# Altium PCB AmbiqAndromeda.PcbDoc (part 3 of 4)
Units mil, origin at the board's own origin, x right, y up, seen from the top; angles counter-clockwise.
Board outline 4055.04 x 2407.2 mil, 6 copper layers (Layer 1, Layer 2, Layer 3, Layer 4, Layer 5, Layer 6), stack 76.457 mil thick; 255 components, 215 nets, 1186 pads, 683 vias.
Unrouted connection lines stored in the file: 258.
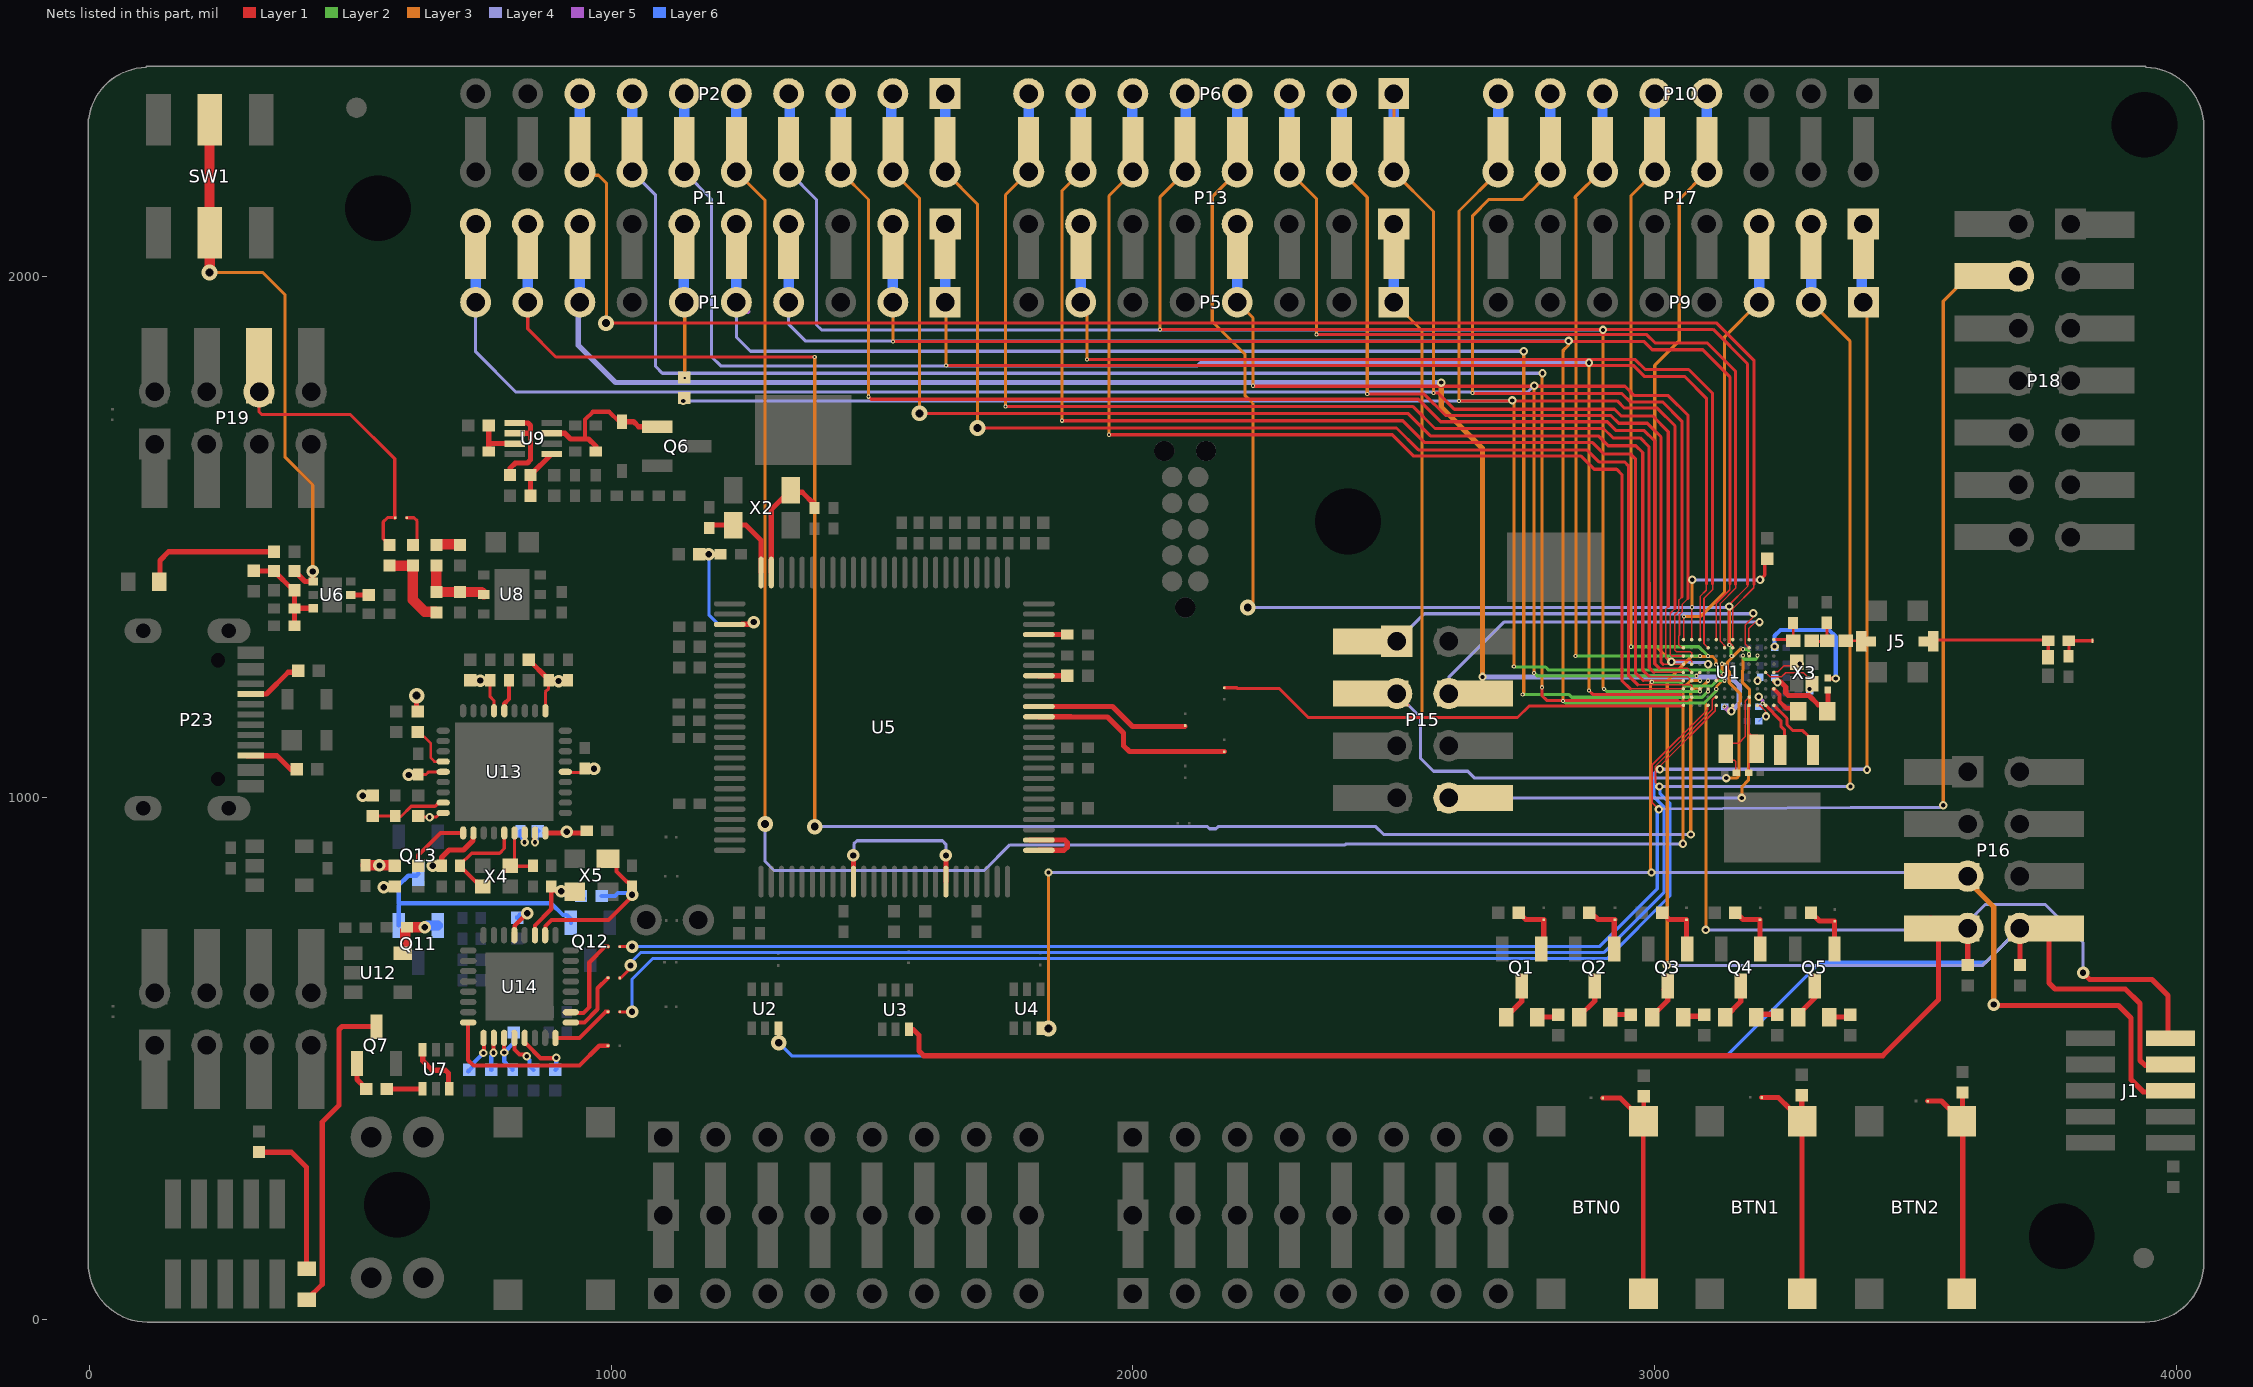
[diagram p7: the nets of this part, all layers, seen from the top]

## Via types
v1: diameter 30, hole 15, Layer 1 to Layer 6, tented both sides, 227 vias
v2: diameter 8, hole 4, Layer 1 to Layer 2, tented both sides, 113 vias
v3: diameter 8, hole 4, Layer 2 to Layer 3, tented both sides, 98 vias
v4: diameter 24, hole 12, Layer 1 to Layer 6, tented both sides, 91 vias
v5: diameter 16, hole 8, Layer 3 to Layer 4, tented both sides, 71 vias
v6: diameter 8, hole 4, Layer 5 to Layer 6, tented both sides, 26 vias
v7: diameter 16, hole 8, Layer 1 to Layer 6, tented both sides, 25 vias
v8: diameter 8, hole 4, Layer 4 to Layer 5, tented both sides, 20 vias
v9: diameter 8, hole 4, Layer 1 to Layer 2, 4 vias
v10: diameter 8, hole 4, Layer 2 to Layer 3, 4 vias
v11: diameter 16/16/16/16/16/16 (per signal layer), hole 8, Layer 1 to Layer 6, tented both sides, 2 vias
v12: diameter 24/0/0/24/24/24 (per signal layer), hole 12, Layer 1 to Layer 6, tented both sides, 1 vias
v13: diameter 30/0/0/30/30/30 (per signal layer), hole 15, Layer 1 to Layer 6, tented both sides, 1 vias

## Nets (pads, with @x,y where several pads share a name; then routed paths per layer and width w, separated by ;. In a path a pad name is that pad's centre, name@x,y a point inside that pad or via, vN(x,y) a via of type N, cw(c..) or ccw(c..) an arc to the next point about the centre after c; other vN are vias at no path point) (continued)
HUB_3.3V: C48.2 C51.2 C59.2 C60.2 C61.2 C62.2 C63.2 C64.2 C65.2 Q11.2 R26.2 R45.2 R46.2 R47.2 R50.2 R59.2 U12.5 U13.5 U13.10 U13.15 U13.23 U13.27 U13.29 U13.36 | length 749.3
  Layer 1 w3: v4@604.36,1047.64 608,1044 v4(612,1044)
  Layer 1 w6: U12.5@600.24,702.4 604.4,702.4 U12.5@605,703 ; v4@606,1046 v4@608,1044 ; v4(612,1044) 629,1044 C61.2@630,1045 645,1045 650,1050 U13.23@677.87,1050 ; R47.2@630,965.31 630,963.35 664.56,963.35 672.48,971.26 U13.27@677.87,971.26 ; C62.2@768,1223.35 768,1193.63 775.31,1186.32 U13.15@775.31,1167.13 ; U13.10@873.74,1167.13 873.74,1203.31 880,1209.57 C65.2@880,1225.31 ; U13.5@912.13,1050 908,1050 907,1049 942.16,1049 949,1055.84 C64.2@949,1056.31
  Layer 1 w10: v1(627,1196) 627,1170.51 ccw(c633.83,1170.51) R50.2@629,1165.69 ; C60.2@675,869.69 675,886 689,900 717.01,900 735.17,918.15 735.17,924.71 735.94,925.49 U13.29@735.94,932.87 ; R45.2@842,1264.69 879.03,1227.65 cw(c876.69,1225.31) C65.2@880,1225.31 ; U13.36@874.61,932 U13.36@873.74,932.87 943.35,932.87 ccw(c943.35,946.96) C59.2@953.31,937
  Layer 1 w20: C48.2@529,870.69 582.59,870.69 cw(c582.59,867.27) R59.2@585,869.69 ; U12.5@605,703 605,745.2 606.87,747.07 606.87,751.84 607.03,752 v4(642.76,752)
  Layer 6 w20: v4(642.76,752) cw(c651.05,743.71) 651.05,755.43 Q11.2@667.4,755.43
  other v4: 658,870 555.79,870.69 915,935 524,1004 967,1056 899,1224 749,1225
  other v7: 652,963
I2SB_NCE46_CT24_SCCRST_PDMC_TX1_SWO_GP46: P5.7 P13.13 U1.H9 | length 2000.4
  Layer 1 w3: U1.H9@3102.33,1287.7 3094.47,1295.55 3094.47,1382.47 3111,1399 3111,1410
  Layer 1 w6: v2(1912,1840) 2963,1840 2982,1821 3065,1821 3111,1775 3111,1410
  Layer 2 w3: P5.7@1891.49,1941.49 P5.7@1900,1950
  Layer 3 w6: P5.7@1900,1950 1912,1938 v2(1912,1840)
  Layer 6 w20: P5.7@1900,1950 1900.16,1950.16 P13.13@1900.16,2100
  other v3: 1912,1840
I2SW_NCE28_CT7_M2MOSI_TX0_GP28: P18.4 SB27.2 U1.A9 | length 4123.8
  Layer 1 w3: v2(3008,978) 2995.5,990.5 2995.5,1063.46 3101.66,1169.62 3101.66,1176.79 U1.A9@3102.33,1177.46
  Layer 1 w6: SB27.2@1016.19,714.88 v4@1039.88,714.88
  Layer 3 w6: v7(3553,986) 3553,990 3553.09,990.09 3553.09,999.43 3553,999.51 3553,1952 3601,2000 P18.4@3697.02,2000
  Layer 4 w6: v8@3009,979 3374.99,981.57 3546.57,981.57 v7@3555,990
  Layer 6 w6: v4(1040,715) 1888.27,715 2894,715 3005,826 3005,974 v6@3009,978 ; P18.4@3694.02,2003 P18.4@3697.02,2000 P18.4@3695.02,1998
  other v3: 3008,978
  other v5: 3008,978
  other v6: 3008,978
  other v8: 3008,978
LV_EN: P19.6 R23.1 SB1.2 | length 575
  Layer 1 w6: P19.6@325,1828.25 P19.6@325,1778.25 325,1740 330,1735 500,1735 585,1650 SB1.2@585,1537.12 ; R23.1@575,1484.69 563,1496.69 563,1529 571.12,1537.12 SB1.2@585,1537.12 ; SB1.2@585,1536 SB1.2@585,1537.12 ; SB1.2@585.81,1537.12 SB1.2@585,1537.12
M0SCL_M0SCK_RTS0_EXHFA_CT8_GP5: P1.6 P11.11 R4.1 | length 297.9
  Layer 1 w20: R4.1@1140,1805.94 1140.93,1805.94 1141,1806 v2(1141,1805)
  Layer 3 w6: v2(1141,1805) P1.6@1141,1949
  Layer 3 w20: P1.6@1140,1950 P1.6@1141,1949
  Layer 6 w10: P1.6@1138.91,1951.09 P1.6@1140,1950
  Layer 6 w20: P1.6@1138.91,1951.09 P11.11@1138.91,2100
  other v3: 1141,1805
M0SDA_M0MISO_CTS0_CT10_I2SD_GP6: P1.5 P11.9 U1.C9 | length 2766.9
  Layer 1 w3: v2(3102,1204) 3102.16,1204.16 3102.16,1208.84 U1.C9@3102.04,1208.96
  Layer 5 w10: P1.5@1257.84,1932.16 P1.5@1262,1932.16
  Layer 2 w6: v3(2747,1198) 2836,1198 2839.81,1194.19 2839.92,1194.19 2841.1,1193 3091,1193 v2(3102,1204)
  Layer 3 w6: v3(2747,1198) 2749,1200 v5(2749,1856)
  Layer 4 w6: P1.5@1240,1950 1240,1883 1267,1856 v5(2749,1856)
  Layer 6 w20: P1.5@1240,1950 P11.9@1240,2100
M1SCL_M1SCK_NCE8_SCCCLK_TX1_GP8: P1.10 P11.19 U1.E10 | length 3190.6
  Layer 1 w3: v2@3078,1234.16 v2@3078.16,1234 ; v2(3080,1234) v2@3078.16,1234 ; U1.E10@3087,1240 3086.58,1240.42 3079.16,1233 v2@3078.16,1234
  Layer 2 w6: v3@2767.91,1239 v3(2768.63,1239.73) 2769.18,1239.73 2774.9,1234 v2(3080,1234)
  Layer 3 w6: v3(2768.63,1239.73) 2768.63,1789.63 v5(2769,1790)
  Layer 4 w6: P1.10@740,1950 740,1855 817,1778 2757,1778 v5(2769,1790)
  Layer 6 w20: P1.10@740,1950 P11.19@740,2100
M1SDA_M1MISO_NCE9_SCCIO_RX1_GP9: P1.9 P11.17 U1.D9 | length 3682.4
  Layer 1 w6: P1.9@840,1950 840,1899 894,1845 v2(1390,1845) ; U1.D9@3101.59,1224 v2(3102.33,1224.71)
  Layer 3 w6: v2(1390,1845) v1(1390,945) v1@1392,943 ; v5(3069,930) 3069,1203 3077,1211 3088.62,1211 v2(3102.33,1224.71)
  Layer 4 w6: v1@1392,938 1399,945 2142.79,945 2146.79,941 2159.21,941 2163.21,945 2465.58,945 2480.58,930 3068,930 v5@3069,929
  Layer 6 w20: P1.9@840,1950 P11.17@840,2100
  other v3: 3102.33,1224.71 1390,1845
MCU_ADCREF: C6.2 P1.8 P11.15 U1.A6 | length 3098.8
  Layer 1 w3: v8(3147,1166) 3147.48,1166.48 3147.48,1171.54 3149.57,1173.63 U1.A6@3149.57,1177.46
  Layer 5 w10: v6(3133.98,1175) 3142.98,1166 v8(3147,1166)
  Layer 3 w10: v5(2591,1796) 2591,1749 2670,1670 v5(2670,1232)
  Layer 4 w10: P1.8@940,1950 937,1947 937,1867 1008,1796 v5(2591,1796) ; v5(2670,1232) 3145,1232 3161.97,1215.03 3161.97,1181.02 v8(3147,1166) v5@3146.37,1166.63
  Layer 6 w20: P1.8@940,1950 P11.15@940,2100
  other v2: 3147,1166
  other v3: 3147,1166
  other v5: 3147,1166
MSPI1_0_NCE51_CT1_GP51: P2.7 P11.14 U1.B11 | length 3163
  Layer 1 w3: 3044.62,1187 3046.31,1185.31 3063.31,1185.31 3070.12,1192.12 3070.12,1192.5 U1.B11@3070.83,1193.21
  Layer 1 w6: v2(2784,1212) 2784,1198 2783,1197 2793,1187 3044.62,1187
  Layer 3 w6: v2(2784,1212) 2784,1813 v5(2785,1814)
  Layer 4 w6: P11.14@1040,2200 1085,2155 1085,1827 1098,1814 v5(2785,1814)
  Layer 6 w3: P2.7@1040,2350 P2.7@1040,2352
  Layer 6 w20: P11.14@1040,2200 P2.7@1040,2350
  other v3: 2784,1212
MSPI1_1_NCE52_CT2_GP52: P2.6 P11.12 U1.B12 | length 3035.5
  Layer 1 w3: 3050.29,1198 U1.B12@3055.08,1193.21
  Layer 1 w6: v2(2874,1206) 2882,1198 3050.29,1198
  Layer 3 w6: v2(2874,1206) 2874,1805 ; 2874,1807 v5(2874,1834)
  Layer 4 w6: P11.12@1140,2200 1192,2148 1192,1846 1210,1828 2123.25,1828 2129.25,1834 v5(2874,1834)
  Layer 6 w20: P2.6@1140,2350 P11.12@1140,2200 P11.12@1144,2204
  other v3: 2874,1206
MSPI1_2_NCE53_CT3_GP53: P2.5 P11.10 U1.D10 | length 3618.7
  Layer 1 w3: U1.D10@3086.58,1223.42 3086,1224 3086.58,1224.58 v2(3086.58,1224.71)
  Layer 3 w6: P11.10@1240,2200 1295,2145 1295,1734.17 ; v1(1295,950) 1295,1732.5 ; v5(3054,912) 3054,1210 3068.71,1224.71 v2(3086.58,1224.71)
  Layer 4 w6: v1(1295,950) 1295,878 1312,861 1715,861 1764,910 2406.65,910 2408.65,912 v5(3054,912)
  Layer 6 w20: P11.10@1240,2200 P2.5@1240,2350
  other v3: 3086.58,1224.71
MSPI1_3_NCE54_CT4_GP54: P2.4 P11.8 U1.C10 | length 2853.7
  Layer 2 w6: v3(2903,1209) 2908,1204 v2(3087,1204)
  Layer 3 w6: v5(2901,1897) 2901,1211 v3(2903,1209)
  Layer 4 w6: P11.8@1340,2200 1393.49,2146.51 1393.49,1906.51 1403,1897 v5(2901,1897)
  Layer 6 w20: P11.8@1340,2200 1342,2202 1342,2333 1340,2335 P2.4@1340,2350
MSPI1_4_NCE55_CT5_GP55: P2.3 P11.6 U1.E11 | length 2649.8
  Layer 1 w3: 3008.64,1248.36 3062.93,1248.36 U1.E11@3070.83,1240.45
  Layer 1 w6: v2(1493,1769) 1498,1764 2547,1764 2590,1721 2909,1721 2926,1704 2980,1704 2999.99,1684.01 2999.99,1257.01 3008.64,1248.36
  Layer 3 w6: P11.6@1440,2200 1493,2147 v2(1493,1769)
  Layer 6 w20: P11.6@1440,2200 P2.3@1440,2350
  other v3: 1493,1769
MSPI1_5_NCE56_CT6_GP56: P2.2 P11.4 U1.D11 | length 2572.9
  Layer 1 w3: 2989.39,1232.61 3062.93,1232.61 U1.D11@3070.83,1224.71
  Layer 1 w6: v1(1591,1737) 2527,1737 2570,1694 2892,1694 2911,1675 2964,1675 2977,1662 2977,1245 2989.39,1232.61
  Layer 3 w6: P11.4@1540,2200 1591,2149 v1(1591,1737)
  Layer 6 w3: P2.2@1537,2346 1540,2349 P2.2@1540,2350
  Layer 6 w20: P2.2@1537,2346 1537,2203 P11.4@1540,2200
MSPI1_6_NCE57_CT7_GP57: P2.1 P11.2 U1.C11 | length 2481.7
  Layer 1 w3: 2967.2,1216.8 3069.07,1216.8 3070.83,1215.05 U1.C11@3070.83,1208.96
  Layer 1 w6: v1(1702,1709) 2505,1709 2547,1667 2870,1667 2893,1644 2942,1644 2950,1636 2950,1234 2967.2,1216.8
  Layer 3 w6: P11.2@1640,2200 1702,2138 v1(1702,1709)
  Layer 6 w20: P11.2@1640,2200 P2.1@1640,2350
MSPI1_7_NCE58_CT8_GP58: P6.8 P13.16 U1.E12 | length 2376.1
  Layer 1 w3: 2998.5,1240.5 3055.04,1240.5 U1.E12@3055.08,1240.45
  Layer 1 w6: v2(1755.75,1750.25) 1756,1750 2537,1750 2579,1708 2902,1708 2920,1690 2972,1690 2989,1673 2989,1413 ; 2989.49,1413 2989.49,1249.51 2998.5,1240.5
  Layer 3 w6: v2(1755.75,1750.25) 1755.75,2155.75 P13.16@1800,2200
  Layer 6 w20: P13.16@1800,2200 P6.8@1800,2349.99
  other v3: 1755.75,1750.25
MSPI1_8_NCE59_CT9_GP59: P6.7 P13.14 U1.D12 | length 2286.6
  Layer 1 w3: 2978,1225 3054.79,1225 U1.D12@3055.08,1224.71
  Layer 1 w6: v2(1864,1723) 2517,1723 2559,1681 2881,1681 2903,1659 2954,1659 2963,1650 2963,1240 2978,1225
  Layer 3 w6: v2(1864,1723) 1864,2164 P13.14@1900,2200
  Layer 6 w6: P13.14@1900,2193 P13.14@1900,2200
  Layer 6 w20: P13.14@1900,2200 P6.7@1900,2349.99
  other v3: 1864,1723
MSPI1_9_NCE60_CT10_GP60: P6.6 P13.12 U1.C12 | length 2210.1
  Layer 1 w3: 2953.04,1208.96 U1.C12@3055.08,1208.96
  Layer 1 w6: v2(1954,1696) 2497,1696 2538,1655 2859,1655 2884,1630 2927,1630 2937,1620 2937,1225 2953.04,1208.96
  Layer 3 w6: v2(1954,1696) 1954,2154 P13.12@2000,2200
  Layer 6 w6: P6.6@1999,2351 P6.6@2000,2349.99
  Layer 6 w20: P6.6@1999,2351 1999,2201 P13.12@2000,2200
  other v3: 1954,1696
MSPI2_0_NCE64_CT14_GP64: P6.2 P13.4 U1.F12 | length 1700.6
  Layer 1 w3: 3016,1256 3054.88,1256 U1.F12@3055.08,1256.2
  Layer 1 w6: v2(2449,1774) 2558.2,1774 2599.2,1733 2916,1733 2931,1718 2986,1718 3012,1692 3012,1260 3016,1256
  Layer 3 w6: P13.4@2400,2200 2449,2151 v2(2449,1774)
  Layer 6 w3: 2395,2319 2395,2344.99 P6.2@2400,2349.99
  Layer 6 w20: P13.4@2400,2200 P6.2@2400,2347.49
  other v3: 2449,1774
MSPI2_1_NCE65_CT15_GP65: P6.1 P13.2 U1.F11 | length 1733.8
  Layer 1 w3: 3026,1367 3021,1362 3021,1268 3024.95,1264.05 3069.07,1264.05 3070.83,1262.29 U1.F11@3070.83,1256.2
  Layer 1 w6: v2(2576,1776) 2585,1776 2616,1745 2923,1745 2936,1732 2996,1732 3026,1702 3026,1367
  Layer 3 w6: P6.1@2500,2349.99 P13.2@2500,2200 2576,2124 v2(2576,1776)
  Layer 6 w6: P6.1@2500,2349.99 2500,2333 P6.1@2504,2329
  Layer 6 w20: P13.2@2500,2200 2500,2325 P6.1@2504,2329
  other v3: 2576,1776
MSPI2_2_NCE66_CT16_GP66: P10.8 P17.16 U1.G12 | length 1522
  Layer 1 w3: 3039,1363 3030,1354 3030,1275 3033,1272 3055.03,1272 U1.G12@3055.08,1271.95
  Layer 1 w6: v2(2625,1761) 2629,1761 2928,1761 2942,1747 3005,1747 3039,1713 3039,1363
  Layer 3 w6: v2(2625,1761) 2625,2125 P17.16@2700,2200
  Layer 6 w20: P17.16@2700,2200 P10.8@2700,2349.99
  other v3: 2625,1761
MSPI2_3_NCE67_CT17_GP67: P10.7 P17.14 U1.G11 | length 1585.2
  Layer 1 w3: 3042,1279.8 3069.07,1279.8 3070.83,1278.04 U1.G11@3070.83,1271.95 ; 3042,1280 3038.5,1283.5 3038.5,1351.01 3046.5,1359.01 3046.5,1379.5 3052,1385
  Layer 1 w6: v2@2650,1776 2651,1775 2937,1775 2953,1759 3015,1759 3052,1722 3052,1385
  Layer 3 w6: v3@2651,1777 2651,2116 2682,2147 2747,2147 P17.14@2800,2200
  Layer 6 w20: P17.14@2800,2200 2800,2337 2804,2341 2800,2345 P10.7@2800,2349.99
  other v2: 2651,1776
  other v3: 2651,1776
MSPI2_4_NCE68_CT18_GP68: P10.6 P17.12 U1.G10 | length 1348.6
  Layer 1 w3: v2(3086.58,1271.95) 3086.58,1271.42 U1.G10@3087,1271
  Layer 2 w6: v3(2848,1272) 2847.1,1272 2848,1272.9 2848.95,1271.95 v2(3086.58,1271.95)
  Layer 3 w6: v3(2848,1272) 2849,1273 2849,2149 2847,2151 2896,2200 P17.12@2900,2200
  Layer 6 w6: P10.6@2900,2349.99 P10.6@2901.99,2349.99
  Layer 6 w20: P17.12@2900,2200 2900,2348 P10.6@2901.99,2349.99
NCE7_M0MOSI_CKO_TRG0_TX0_CT19_GP7: P1.4 P11.7 U1.C8 | length 2711
  Layer 1 w3: P11.7@1340,2100 P11.7@1346.2,2100
  Layer 2 w6: v3(2824,1186) 2828,1182 3095,1182 3118,1205 v2(3118,1209)
  Layer 3 w6: v3(2824,1186) 2824,1855 2825,1856 2824,1857 2835,1868 v5(2835,1876)
  Layer 4 w6: P1.4@1340,1950 1340,1908 1372,1876 v5(2835,1876)
  Layer 6 w20: P1.4@1340,1950 P11.7@1340,2100
NCE41_BLEIRQ_SWO_I2SW_RTS1_TX0_RTS0_GP41: J1.6 P16.5 U1.D7 U4.3 | length 3378.9
  Layer 1 w6: v1@1838,556 v1(1838,558)
  Layer 1 w10: P16.5@3550,850 P16.5@3600,850 ; v4(3650,604) 3652,602 3889,602 3913,578 3913,460 3936.58,436.42 3986.19,436.42 J1.6@3988.77,439
  Layer 2 w6: v3(2994.5,1222.5) 3048.05,1222.5 3056.05,1214.5 3109.06,1214.5 3119.26,1224.71 v2(3133.82,1224.71)
  Layer 3 w6: v1(1838,558) v5(1838,857) ; v5(2994,857) 2992,859 2992,1219.46 2994.5,1221.96 v3(2994.5,1222.5)
  Layer 3 w10: P16.5@3605.31,835.63 3650,790.94 v4(3650,604)
  Layer 4 w6: v5(1838,857) v5(2994,857) 3593,857 P16.5@3600,850
  Layer 6 w10: P16.5@3600,850 3604.92,850 3605.31,850.39 P16.5@3605.31,835.63
NetA1_1: A1.1 C41.2 C42.1 | length 78.7
  Layer 1 w6.25: C41.2@3790.78,1301.32 C41.2@3794,1301.32 ; C42.1@3793,1271.69 3793,1272.65 3794,1273.65 C41.2@3794,1301.32 ; C41.2@3793.69,1301 C41.2@3794,1301.32 ; A1.1@3839.02,1301.32 C41.2@3794,1301.32
NetBTN0_2: BTN0.2 BTN0.3 R36.1 SB24.2 | length 479.6
  Layer 1 w8: BTN0.3@2953.06,405.88 2955.02,405.88 BTN0.3@2978,382.91 ; BTN0.2@2978.58,49.65 2978,50.23 BTN0.3@2978,382.91 ; R36.1@2979,428.32 2979,380.77 BTN0.3@2978.58,380.35 2978.58,382.32 BTN0.3@2978,382.91
  Layer 1 w10: SB24.2@2900.19,424.88 2934.06,424.88 BTN0.3@2953.06,405.88
NetBTN1_2: BTN1.2 BTN1.3 R37.1 SB25.2 | length 472.4
  Layer 1 w10: SB25.2@3205.19,425.88 3207.18,425.88 3207.3,426 3236.94,426 3258.06,404.88 3260.02,404.88 BTN1.3@3282,382.91 ; R37.1@3282,427.07 BTN1.3@3282,382.91 ; BTN1.2@3282.58,49.65 BTN1.3@3282.58,380.35 3282.58,382.32 BTN1.3@3282,382.91
NetBTN2_2: BTN2.2 BTN2.3 R38.1 SB26.2 | length 799.6
  Layer 1 w10: SB26.2@3523.19,418.88 3523.98,418.88 3524.1,419 3549.94,419 3564.06,404.88 3566.02,404.88 3588.58,382.32 BTN2.3@3588.58,380.35 ; BTN2.2@3588.58,49.65 3590,51.06 R38.1@3590,435.32 ; BTN2.2@3590.58,45.65 BTN2.3@3590.58,376.35
NetC7_2: C7.2 U1.A3 | length 48.9
  Layer 1 w3: U1.A3@3196.81,1177.46 3197.52,1176.75 3202.17,1176.75 3213.25,1165.68 v2(3213.25,1156.25)
  Layer 6 w3: C7.2@3199.33,1147.04 3200.12,1147.04 3204.92,1151.84 3204.92,1152.63 3207.88,1155.6 3212.6,1155.6 v2(3213.25,1156.25)
  other v3: 3213.25,1156.25
  other v5: 3213.25,1156.25
  other v6: 3213.25,1156.25
  other v8: 3213.25,1156.25
NetC8_2: C8.2 U1.B3 | length 19
  Layer 1 w3: U1.B3@3196.81,1193.21 3197.63,1194 v2(3199.31,1194)
  Layer 5 w6: v2(3199.31,1194) 3207,1186.31 v6(3207,1181)
  other v3: 3199.31,1194
  other v5: 3199.31,1194
  other v8: 3199.31,1194
NetC9_2: C9.2 U1.D3 | length 3.4
  Layer 4 w6: v8(3197.05,1224.71) 3198.47,1224.71 3197.76,1224 v8(3197.05,1224.71)
  other v2: 3197.05,1224.71
  other v3: 3197.05,1224.71
  other v5: 3197.05,1224.71
  other v6: 3197.05,1224.71
NetC26_2: C26.2 U5.47 | length 54.7
  Layer 1 w10: U5.47@1819.63,1312.96 C26.2@1874.31,1313 ; C26.2@1874.31,1313 C26.2@1874.31,1313
NetC27_1: C27.1 U5.74 X2.3 | length 237
  Layer 1 w10: U5.74@1306.83,1432.05 1306.83,1552.64 X2.3@1343.84,1589.64 1347.49,1586 1366.26,1586 1389.72,1562.54 C27.1@1389.72,1555.55
NetC28_1: C28.1 U5.75 X2.1 | length 175.5
  Layer 1 w10: C28.1@1187.72,1517.49 1188.49,1517.49 1194,1523 1257.92,1523 1287.15,1493.77 U5.75@1287.15,1432.05
NetC29_2: C29.2 R14.1 U5.78 | length 279
  Layer 1 w10: R14.1@1164.8,1467 v4(1187.06,1467) ; U5.78@1227.11,1332.64 U5.78@1247.33,1332.64 ; U5.78@1250.68,1333 1269,1333 v12(1273,1337)
  Layer 5 w10: v12@1268,1334 1269,1333 v12(1273,1337)
  Layer 6 w6: v4(1187.06,1467) 1187.06,1350.94 1205,1333 v12@1269,1333
NetC30_2: C30.2 C31.2 FB1.2 R17.2 R18.2 U6.6 | length 198.4
  Layer 1 w10: FB1.2@314,1434.99 R18.2@353.55,1434.99 ; R18.2@353.55,1434.99 390.5,1397.99 R17.2@392.92,1397.99 C31.2@392.92,1362.99 ; C30.2@392.92,1329.99 C31.2@392.92,1362.99 ; U6.6@428.89,1363.41 393.33,1363.41 C31.2@392.92,1362.99
NetC37_2: C37.2 L2.1 R29.2 U1.D1 | length 181
  Layer 1 w4: U1.D1@3228.31,1224.71 U1.D1@3229.04,1224.71 ; v2(3235.5,1221.5) 3235.97,1221.5 v2@3236.23,1221.77
  Layer 1 w6: U1.D1@3228.31,1224.71 3231.02,1222
  Layer 1 w10: 3231.02,1222 3241.59,1222 3251.26,1212.33 3251.26,1200.95 3255.94,1196.26 3295.74,1196.26 3313.59,1178.41 3319.63,1178.41 3326,1172.04 3326,1165 3326.7,1165.7 L2.1@3330.37,1165.7 3332,1167.32 R29.2@3332,1206.58
  other v3: 3235.5,1221.5
  other v5: 3235.5,1221.5
  other v6: 3235.5,1221.5
  other v8: 3235.5,1221.5
NetC38_2: C38.2 R29.1 U1.H1 | length 248.9
  Layer 1 w8: R29.1@3332,1229.42 3332.42,1229 v7(3347,1229)
  Layer 6 w8: v2(3229.79,1290.12) 3231,1288.91 C38.2@3229.79,1287.7 3229.79,1310.79 3241,1322 3334,1322 3347,1309 v7(3347,1229)
  other v3: 3229.79,1290.12
  other v5: 3229.79,1290.12
  other v6: 3229.79,1290.12
  other v8: 3229.79,1290.12
NetC39_1: C39.1 L3.1 U1.J1 | length 77.5
  Layer 1 w5: L3.1@3265.53,1301.32 3265.53,1303.7 3265.53,1339.84 C39.1@3266,1340.32
  Layer 1 w5.51: U1.J1@3229.79,1303.7 L3.1@3263.15,1303.7
  Layer 1 w6.25: U1.J1@3228.31,1303.45 3229.54,1303.45 U1.J1@3229.79,1303.7 ; L3.1@3263.15,1303.7 L3.1@3265.53,1301.32
NetC40_1: C40.1 L3.2 L4.1 | length 65.7
  Layer 1 w5.51: L4.1@3330,1302.23 C40.1@3330,1335.63
  Layer 1 w6.25: L3.2@3300.96,1301.32 3303.68,1301.32 3305,1300 3329.59,1300 L4.1@3330.91,1301.32 L4.1@3330,1302.23
NetC41_1: C41.1 J5.2 L5.2 | length 252.4
  Layer 1 w5.51: J5.2@3536.9,1303 C41.1@3753.67,1303
  Layer 1 w6.25: J5.2@3533.9,1300 J5.2@3536.9,1303 ; L5.2@3754,1269.72 3754.31,1270.03 C41.1@3754.31,1301
NetC43_1: C43.1 U1.E1 X3.3 | length 81
  Layer 1 w3: U1.E1@3228.31,1240.45 3229.34,1241.49 3235.91,1241.49 3247.93,1253.5 3270.5,1253.5 X3.3@3271.37,1254.37 ; X3.3@3272.05,1260.37 3272.05,1255.05 X3.3@3271.37,1254.37 ; v2(3278,1257) 3281,1260 3279,1262 3277,1260 X3.3@3271.37,1254.37
  Layer 4 w3: v2(3278,1257) 3278,1258 3281,1261 v5@3279,1263
  other v3: 3278,1257
  other v5: 3278,1257
  other v6: 3278,1257
  other v8: 3278,1257
NetC44_1: C44.1 U1.E2 X3.1 | length 108.7
  Layer 1 w3: U1.E2@3212.56,1240.45 3220.41,1232.61 3243.61,1232.61 3251,1240 3285,1240 3296,1229 X3.1@3296,1214.61
  other v2: 3297,1209
  other v3: 3297,1209
  other v5: 3297,1209
  other v6: 3297,1209
  other v8: 3297,1209
NetC46_1: C46.1 U1.B4 X1.2 | length 183.1
  Layer 1 w3: X1.2@3131,1105 3161,1105 3173.16,1117.17 3173.16,1185.31 U1.B4@3181.07,1193.21 ; X1.2@3136.47,1094 3136.47,1084.76 3148.75,1072.48 3152.99,1072.48 3155,1070.47 3155,1049 C46.1@3156.02,1048
NetC47_1: C47.1 U1.A4 X1.1 | length 124.4
  Layer 1 w3: C47.1@3179.98,1048 3181,1048 3181,1066.18 3182.76,1067.94 3183.25,1067.94 3195.53,1080.22 X1.1@3195.53,1094 ; U1.A4@3181.07,1177.46 3181.07,1123.93 3185,1120 X1.1@3197,1120
NetC54_2: C54.2 R46.1 U13.26 | length 146.2
  Layer 1 w6: R46.1@543,965.32 C54.2@586.03,965.31 586.86,964.49 597.06,964.49 616.69,984.11 662.58,984.11 669.41,990.94 U13.26@677.87,990.94
NetC55_1: C55.1 U13.33 X4.3 | length 110.5
  Layer 1 w6: U13.33@814.69,932.87 814.69,877.8 X4.3@806.57,869.69 807.26,869 849.32,869 C55.1@850,869.69
NetC56_1: C56.1 U13.32 X4.1 | length 190.7
  Layer 1 w6: C56.1@710,869.69 710,871.65 732.35,894 786,894 795,903 U13.32@795,932.87
  Layer 1 w8: C56.1@710,869.69 710,867.72 715.84,861.87 717.81,861.87 739.59,840.09 743.65,840.09 X4.1@753.43,830.32
NetC57_2: C57.2 U13.34 | length 24.6
  Layer 6 w8: C57.2@826,936.31 826,927 830,923 830,921.16 834,917.16 v7(834,915)
NetC58_2: C58.2 U13.14 | length 61.9
  Layer 1 w8: U13.14@795,1167.13 795,1180.57 804,1189.57 804,1209.57 804,1217.44 C58.2@804,1225.31
NetC66_2: C66.2 R54.1 U14.3 | length 139
  Layer 1 w8: U14.3@794,548 794,537 U14.3@794.5,537.5 ; U14.3@794.5,526.5 U14.3@794.5,537.5 ; v7(795,512) 794.68,512.32 U14.3@794.68,540 794.5,539.82 U14.3@794.5,537.5
  Layer 6 w8: C66.2@811,478.69 811,480.65 805.16,486.5 803.19,486.5 795,494.69 v7(795,512) 813,530 R54.1@813,549
NetC67_1: C67.1 R58.2 U14.19 X5.1 | length 206.6
  Layer 1 w8: U14.19@853.74,737 853.74,755.74 885,787 C67.1@885,828.35 ; C67.1@885,830.32 C67.1@885,828.35 ; X5.1@930,820 895.53,820 893.02,822.5 890.84,822.5 C67.1@885,828.35
  Layer 6 w8: v4@904,822 913,813 941.34,813 R58.2@942.21,812.13 942.21,807.81 942.89,807.13 R58.2@947.21,807.13
  other v4: 904,821
NetC68_1: C68.1 R58.1 U14.18 X5.3 | length 363
  Layer 1 w8: U14.18@874.15,737.58 874.15,754.54 885.62,766 995,766 1040,811 v4(1040,814.57) C68.1@1040,830.32 1040,832.28 1034.16,838.13 1032.19,838.13 1030.31,840 1029,840 1010.06,858.94 1010.06,869.28 996.35,882.99 X5.3@993.78,882.99
  Layer 6 w8: R58.1@981.58,812.13 1007.13,812.13 1013,818 1036.57,818 v4(1040,814.57)
NetC78_2: C78.2 R79.2 U9.3 | length 103.1
  Layer 1 w10: C78.2@765.19,1663.9 765.19,1679.06 ; R79.2@765.19,1713.9 764.46,1713.9 761.86,1711.3 765.19,1707.97 765.19,1679.06 ; U9.3@815.07,1679.06 765.19,1679.06
NetC80_2: C80.2 D70.1 Q6.1 U9.7 | length 298.3
  Layer 1 w8: 950,1688 950,1725.26 964.74,1740 996.14,1740 1015,1721.14 D70.1@1020.5,1721.14
  Layer 1 w10: U9.7@885.93,1698.74 911.26,1698.74 922,1688 950,1688 956.4,1688 970.5,1673.9 970.19,1673.58 C80.2@970.19,1663.9 ; D70.1@1020.5,1721.14 1042.9,1721.14 1052.74,1711.3 Q6.1@1088.1,1711.3
NetD2_2: D2.2 R19.2 | length 267.2
  Layer 1 w10: D2.2@133.53,1414 135,1415.47 135,1455 151.99,1471.99 R19.2@353.55,1471.99
NetD3_1: D3.1 Q7.3 | length 617.7
  Layer 1 w10: D3.1@416,38.47 416.47,38.47 446,68 446,379 478,411 478,555.83 483.86,561.68 Q7.3@550,561.68
NetD3_2: D3.2 R27.1 | length 297.6
  Layer 1 w10: R27.1@325,321.32 325.31,321 387,321 416,292 D3.2@416,97.53
NetD5_1: D5.1 Q1.3 | length 71.8
  Layer 1 w10: D5.1@2715.47,580 2715.47,580.16 2745,609.69 Q1.3@2745,639.57
NetD5_2: D5.2 R31.1 | length 42.4
  Layer 1 w10: D5.2@2774.53,580 2810.32,580 R31.1@2815,584.69
NetD6_1: D6.1 Q2.3 | length 71.8
  Layer 1 w10: D6.1@2855.47,580 2855.47,581.47 2885,611 Q2.3@2885,639.57
NetD6_2: D6.2 R32.1 | length 50.2
  Layer 1 w10: D6.2@2914.53,580 2910.28,580 2910.12,580.16 2914.65,584.69 R32.1@2954,584.69
NetD7_1: D7.1 Q3.3 | length 84.9
  Layer 1 w10: D7.1@2995.47,580 2993,580 3018.24,605.24 3025,612 Q3.3@3025,639.57 Q3.3@3018.24,632.81
NetD7_2: D7.2 R33.1 | length 42.4
  Layer 1 w10: D7.2@3054.53,580 3056,581.47 3091.79,581.47 R33.1@3095,584.69
NetD8_1: D8.1 Q4.3 | length 71.8
  Layer 1 w10: D8.1@3135.47,580 3165,609.53 Q4.3@3165,639.57
NetD8_2: D8.2 R34.1 | length 52.5
  Layer 1 w10: D8.2@3194.53,580 3194.53,580.88 3190.04,585.37 3234.31,585.37 R34.1@3235,584.69
NetD9_1: D9.1 Q5.3 | length 72.7
  Layer 1 w10: D9.1@3275.47,580 3275.47,585.37 3307.07,616.97 Q5.3@3307.07,639.57
NetD9_2: D9.2 R35.1 | length 42.4
  Layer 1 w10: D9.2@3334.53,580 3370.32,580 R35.1@3375,584.69
NetJ5_1: J5.1 L4.2 | length 30.3
  Layer 1 w5.51: L4.2@3366.35,1301.32 J5.1@3394.78,1301.32
  Layer 1 w6.25: J5.1@3394.78,1301.32 J5.1@3396.1,1300
NetL1_1: L1.1 U1.A2 | length 104.1
  Layer 1 w6: U1.A2@3212.56,1177.46 3241.87,1148.15 3241.87,1137.13 3249,1130 3249,1100.5 L1.1@3240.5,1092
NetL1_2: L1.2 U1.A1 | length 96.5
  Layer 1 w6: U1.A1@3228.31,1177.46 3228.5,1177.46 3253.51,1152.45 3253.51,1140.49 3265,1129 3284,1129 L1.2@3293.7,1119.3
NetL2_2: L2.2 U1.C1 | length 72.6
  Layer 1 w8: U1.C1@3228.31,1208.96 3239.26,1198.01 3239.26,1184.74 3252.19,1171.81 3269.15,1171.81 L2.2@3275.26,1165.7
NetP23_A5: P23.A5 R44.2 | length 95.7
  Layer 1 w10: P23.A5@309.27,1199.21 339.21,1199.21 381,1241 387.69,1241
NetP23_B5: P23.B5 R43.2 | length 111.2
  Layer 1 w10: P23.B5@309.27,1081.1 301.9,1081.1 302,1081 359,1081 385.67,1054.33 R43.2@394.67,1054.33
NetQ1_1: Q1.1 R28.2 SB19.2 | length 115.4
  Layer 1 w10: R28.2@2736,779.61 2736.39,780 R28.2@2739.69,780 2752.87,766.81 SB19.2@2787.38,766.81 2787.38,715.41 Q1.1@2782.4,710.43
NetQ2_1: Q2.1 R30.2 SB20.2 | length 111.7
  Layer 1 w10: R30.2@2874.69,780 2878.39,780 2891.58,766.81 SB20.2@2923.88,766.81 2922.4,765.33 Q2.1@2922.4,710.43
NetQ3_1: Q3.1 R39.2 SB21.2 | length 113
  Layer 1 w10: R39.2@3015.49,776 3014.69,776.81 R39.2@3014.69,780 3027.87,766.81 SB21.2@3060.88,766.81 3060.88,711.95 Q3.1@3062.4,710.43
NetQ4_1: Q4.1 R40.2 SB22.2 | length 109.3
  Layer 1 w10: R40.2@3154.69,780 3155.96,780 3169.15,766.81 SB22.2@3201.88,766.81 3201.88,710.95 Q4.1@3202.4,710.43
NetQ5_1: Q5.1 R41.2 SB23.2 | length 125.6
  Layer 1 w10: R41.2@3299.69,780 3315.87,763.81 SB23.2@3344.88,763.81 3344.88,710.84 Q5.1@3344.47,710.43 3344.47,728.53 Q5.1@3343,730
NetQ7_1: Q7.1 R42.2 | length 56.2
  Layer 1 w10: Q7.1@512.6,490.82 512.6,460.4 530.31,442.69 R42.2@530.31,442
NetQ11_1: Q11.1 Q12.1 Q13.3 R59.1 | length 499.6
  Layer 6 w8: v4(564,829) 567.06,832.06 576.15,832.06 576.69,832.6 592.6,832.6 ; Q11.1@592.6,755.43 592.6,794.02 ; Q13.3@630,854.57 626.31,850.88 610.88,850.88 592.6,832.6 ; Q12.1@922.6,760.43 922.6,767.77 914.79,775.58 907.45,775.58 885.03,798 592.6,798 592.6,832.6
NetR4_2: R4.2 U1.D8 | length 2529.2
  Layer 1 w3: U1.D8@3118.07,1224.71 3128.36,1234.99 3130.64,1234.99 3132.65,1237 v2(3132,1237)
  Layer 2 w6: v3(2730,1252) 2731,1251 2791,1251 2797,1245 3124,1245 v2(3132,1237)
  Layer 3 w6: v3(2727,1762) 2730,1759 v3(2730,1252)
  Layer 4 w6: v2(1138,1761) 2726,1761 v3(2727,1762)
  other v3: 1138,1761
  other v5: 1138,1761 2727,1762
NetR5_2: R5.2 U1.J11 | length 291.1
  Layer 1 w3: v2(3071.81,1365.4) 3071.2,1364.8 3071.2,1305.41 U1.J11@3072,1304.62
  Layer 1 w6: v2(3202,1418) 3211,1427 3211,1453.31 R5.2@3216,1458.31
  Layer 3 w6: v2(3071.81,1365.4) v5@3071.81,1418 ; v5(3072,1418) v5@3072,1419
  Layer 4 w6: v5(3072,1418) v2(3202,1418)
  other v3: 3071.81,1365.4 3202,1418
  other v5: 3202,1418
NetR13_2: R13.2 U5.43 | length 54.8
  Layer 1 w10: U5.43@1819.63,1234.22 1874.1,1234.22 R13.2@1874.31,1234
NetR18_1: R18.1 SW1.2 SW1.5 U6.4 | length 1104
  Layer 1 w10: R18.1@392.92,1434.99 413.32,1414.59 U6.4@428.89,1414.59 430.59,1414.59 431,1415 428,1418 v4(428,1434)
  Layer 1 w20: v1(230,2007) 230,2006 230.57,2006.57 SW1.5@230.57,2083 ; SW1.5@230,2066 SW1.2@230,2310
  Layer 3 w6: v1(230,2007) 332,2007 375,1964 375,1653 428,1600 v4(428,1434)
NetR20_1: R20.1 U6.2 | length 34.6
  Layer 1 w10: U6.2@500.93,1389 R20.1@535.54,1389
NetR21_1: R21.1 SB1.1 | length 71.9
  Layer 1 w6: SB1.1@608.19,1537 622,1537 628,1531 628,1492.69 R21.1@620,1484.69
NetR21_2: R21.2 R23.2 R61.2 | length 165.9
  Layer 1 w20: R23.2@575,1445.31 R21.2@620,1445.31 620,1380 642.87,1357.13 663.19,1357.13 R61.2@665,1355.31 R61.2@665,1355
NetR22_1: R22.1 R60.2 | length 46.5
  Layer 1 w20: R60.2@665,1484.69 666.81,1486.5 698.71,1486.5 708.19,1486.5 R22.1@710,1484.69
NetR42_1: R42.1 U7.4 | length 69
  Layer 1 w10: R42.1@569.68,442 637.81,442 U7.4@638.41,442.6
NetR49_2: R49.2 U13.35 | length 42.4
  Layer 1 w6: U13.35@854.06,932.87 854.87,932.87 U13.35@854.46,932.46
  Layer 1 w10: U13.35@853,932 cw(c853,931) 854,931 v11(854,915)
  Layer 6 w10: v11(854,915) 855.15,916.15 855.15,932.46 R49.2@859,936.31
NetR52_2: R52.2 U14.21 | length 76.5
  Layer 1 w8: U14.21@814.37,736.85 814.37,737.06 814,737.43 815.1,738.52 815.1,755.1 v4(839,779)
  Layer 6 w8: R52.2@820,770 820,771.97 823.97,775.94 835.94,775.94 v4(839,779)
NetR53_1: R53.1 U14.2 | length 63.4
  Layer 1 w8: v7(774.5,511.5) 774.5,539.5 U14.2@775,540
  Layer 6 w8: R53.1@770,478.69 770,504.84 774.5,509.34 v7(774.5,511.5)
NetR55_2: R55.2 U14.5 | length 108.1
  Layer 1 w8: U14.5@833,539 U14.5@833.33,538.67 ; U14.5@834.06,540 834.06,531.19 836.99,528.25 837.39,528.25 864.65,501 893.5,501 v7(894.5,502) v7@896,502
  Layer 6 w8: R55.2@893,478.69 894.5,480.19 v7(894.5,502)
NetR56_2: R56.2 U14.4 | length 86.3
  Layer 1 w8: U14.4@814.37,540 814.37,517.63 824,508 837,508 v7@841,504
  Layer 6 w8: v7(838,505) 838,502.84 843.19,497.65 843.19,486.5 R56.2@851,478.69
NetR57_1: R57.1 U14.1 | length 75.3
  Layer 1 w8: v7@756,511 U14.1@756,539.32
  Layer 6 w8: R57.1@726,476 728,478 R57.1@728,478.69 735.81,486.5 735.81,491.81 v7(755,511)
NetR60_1: R60.1 R61.1 R62.2 U8.5 | length 143.4
  Layer 1 w20: R60.1@665,1445.32 R61.1@665,1394.69 R62.2@710,1394.69 751.18,1394.69 U8.5@755.87,1390
NetR80_1: R80.1 U9.1 U9.2 | length 187.6
  Layer 1 w10: R80.1@805.82,1618.9 805.82,1631.72 816.22,1642.13 839.56,1642.13 845.46,1648.03 845.46,1698.74 ; U9.2@815.07,1698.74 845.46,1698.74 ; U9.1@815.07,1718.43 840.66,1718.43 845.46,1713.62 845.46,1698.74
NetR80_2: R80.2 R81.2 U9.5 | length 97.5
  Layer 1 w10: R81.2@845.19,1578.9 R80.2@845.19,1618.9 845.46,1618.9 U9.5@885.93,1659.37
NetSB3_1: SB3.1 U14.32 | length 360.3
  Layer 1 w8: U14.32@725.79,569.53 725.79,497.21 736,487 939,487 977,525 SB3.1@993.81,525
NetSB17_1: SB17.1 U14.8 | length 121.4
  Layer 1 w8: U14.8@893.11,540 939,540 989,590 SB17.1@993.81,590
NetSB18_1: SB18.1 U14.9 | length 130.1
  Layer 1 w8: U14.9@922.64,569.53 948.53,569.53 974,595 974,635.19 SB18.1@993.81,655
NetSB27_1: SB27.1 U14.10 | length 174.7
  Layer 1 w8: U14.10@922.64,589.21 923.37,588.48 935.9,588.48 936.39,588 947,588 958,599 958,685 988,715 SB27.1@993.81,715
NetU5_10: U5.10 U5.19 | length 314
  Layer 1 w10: v4(1464,889.75) 1464,886 1464.31,885.68 U5.10@1464.31,839.53 ; U5.19@1641.48,839.53 v4(1641.48,889.75)
  Layer 4 w6: 1465,902 1465,912 1471,918 1634.96,918 1641.48,911.48 v4(1641.48,889.75)
NetU5_26: U5.26 U5.27 | length 139.5
  Layer 1 w10: U5.27@1802.08,919.25 U5.27@1819.63,919.25 1869.26,919.25 1873.89,914.62 1873.89,905.57 1873.57,905.57 1867.57,899.57 U5.26@1819.63,899.57
NetU7_3: U7.3 U7.6 | length 110.7
  Layer 1 w10: U7.3@638.41,517.4 638.95,516.87 638.95,496.05 657,478 682.14,478 688,472.14 688,444.19 U7.6@689.59,442.6
NON_REM0: R51.2 U13.28 | length 122.4
  Layer 1 w8: R51.2@630,871.65 630,890 672.87,932.87 U13.28@716.26,932.87
NON_REM1: R50.1 U13.22 | length 88.7
  Layer 1 w5: R50.1@629,1126.32 638.31,1117 642,1117 654,1105 654,1077 661.31,1069.69 U13.22@677.87,1069.69
RTS: SB13.1 U5.39 | length 397.3
  Layer 1 w6: 1881.34,1155.48 1881.61,1155.2
  Layer 1 w10: U5.39@1819.63,1155.48 1881.34,1155.48 ; 1881.61,1155.2 1951.3,1155.2 1981.99,1124.51 1981.99,1100 1993.17,1088.81 SB13.1@2175,1088.81
RTS0_SCE_NCE3_MSPI7_TRG1_I2SW_GP3: P15.8 U1.G3 | length 885
  Layer 2 w6: v3(3169,1273) 3169,1269 3172.11,1265.89 3193.89,1265.89 3197,1269 v2(3197,1273)
  Layer 3 w6: v5(3167,1000) 3167,1021 3179.57,1033.57 3179.57,1175.4 3182,1177.83 3182,1207.23 3168.62,1220.61 3168.62,1244.35 3169,1244.73 v3(3169,1273)
  Layer 4 w6: P15.8@2605.51,1000 v5(3167,1000)
RTS1_NCE44_CT20_M4MOSI_TX0_GP44: P1.1 P11.1 U1.J10 | length 2222.6
  Layer 1 w3: U1.J10@3086.58,1303.45 3087,1303.87 3087,1386 3099,1398 3099,1410
  Layer 1 w6: v2(1642,1829) 2959,1829 2980,1808 3057,1808 3099,1766 3099,1410
  Layer 3 w6: P1.1@1640,1950 1642,1948 v2(1642,1829)
  Layer 6 w20: P1.1@1640,1950 P11.1@1640,2100
  other v3: 1642,1829
RX0_NCE23_CT14_I2SW_CMP0_MSPI3_EXXT_GP23: P5.1 P13.1 SB12.2 U1.A12 | length 1894.6
  Layer 1 w6: SB12.2@2175.12,1211.19 2198.81,1211.19 2200,1210 2280,1210 2336,1154 v3(2554,1154) 2737,1154 2759,1176 3053.62,1176 U1.A12@3055.08,1177.46
  Layer 5 w3: P5.1@2500,1934 P5.1@2500,1950
  Layer 3 w6: P5.1@2500,1950 2554,1896 v3(2554,1154)
  Layer 6 w3: P5.1@2498,1958 P5.1@2500,1956
  Layer 6 w20: P5.1@2500,1956 2500.16,1956.16 P13.1@2500.16,2100
  other v2: 2554,1154
RX0_NCE27_CT5_M2SCL_M2SCK_GP27: P9.2 P17.3 SB17.2 U1.B8 | length 4075.3
  Layer 1 w3: v2(3009,1022) 3001.5,1029.5 3001.5,1060.97 3110.17,1169.65 3110.17,1188.17 3115,1193 3117.86,1193 U1.B8@3118.07,1193.21
  Layer 1 w6: SB17.2@1016.19,589.88 1039.88,589.88 v4(1040,590)
  Layer 2 w6: P9.2@3291.27,1939.73 3291.27,1941.27 P9.2@3300,1950
  Layer 3 w6: P9.2@3300,1950 3374,1876 v7@3374,1026.51
  Layer 4 w6: v2(3009,1022) v7(3375,1022)
  Layer 6 w6: v4(1040,590) 1040,653 1079,692 2909,692 3029,812 3029,990 3010,1009 3010,1023 v2(3009,1022)
  Layer 6 w20: P9.2@3300,1950 3294,1956 3300,1962 P17.3@3300,2100
  other v3: 3009,1022
  other v5: 3009,1022
  other v6: 3009,1022
  other v8: 3009,1022
RX0_NCE49_CT30_M5SDA_M5MISO_GP49: P5.4 P13.7 U1.H12 | length 1670.8
  Layer 1 w3: U1.H12@3055.08,1287.7 3051.67,1287.7 3046,1293.37 3046,1310.18 3047.5,1311.68 3047.5,1351.52 3052.5,1356.52 3052.5,1370.5 3064,1382
  Layer 1 w6: P5.4@2195,1952 P5.4@2201,1946 ; v2@2230,1789 2943,1789 2961,1771 3026,1771 3064,1733 3064,1382
  Layer 5 w3: P5.4@2200,1929 P5.4@2200,1950
  Layer 3 w3: P5.4@2199,1951 P5.4@2200,1950
  Layer 3 w6: P5.4@2200,1950 2230,1920 v2(2230,1790)
  Layer 6 w6: P5.4@2199,1951 P5.4@2200,1950
  Layer 6 w20: P5.4@2199,1951 2198,1952 2200.16,1954.16 P13.7@2200.16,2100
  other v3: 2230,1790
RX0_RX1_TRG0_M4SDA_M4MISO_GP40: P9.3 P17.5 U1.J12 | length 875.4
  Layer 1 w3: U1.J12@3055.08,1303.45 3055,1303.53 3056,1304.53 v2(3056,1348)
  Layer 3 w6: v2(3056,1348) 3088,1348 3134,1394 3134,1884 P9.3@3200,1950
  Layer 6 w20: P9.3@3200,1950 P17.5@3200,2100
  other v3: 3056,1348
RX1_NCE25_CT1_M2SDA_M2MISO_GP25: P9.1 P17.1 SB18.2 U1.A8 | length 3945.4
  Layer 1 w3: v2(3010,1055) 3010,1060.99 3116.17,1167.16 3116.17,1175.56 U1.A8@3118.07,1177.46
  Layer 1 w6: SB18.2@1016.19,654.88 1018.18,654.88 1037,673.7 v4(1037,679)
  Layer 5 w20: P9.1@3397,1953 P9.1@3400,1950
  Layer 3 w6: v7(3407,1054) P9.1@3407,1942.03
  Layer 4 w6: v2(3010,1055) 3406,1055 v7(3407,1054)
  Layer 6 w6: v4(1037,679) 1037,684 1057,704 2903,704 3018,819 3018,982.14 2999,1001.14 2999,1047 3007,1055 v2(3010,1055) ; P9.1@3400,1950 3407.49,1942.51 P9.1@3407,1942.03
  Layer 6 w20: P17.1@3397,2100 3397,1953 P9.1@3400,1950
  other v3: 3010,1055
  other v5: 3010,1055
  other v6: 3010,1055
  other v8: 3010,1055
RX1_NCE43_CT18_M3SDA_M3MISO_GP43: P1.2 P11.3 U1.J8 | length 2371.5
  Layer 1 w3: U1.J8@3118.07,1303.45 3118.07,1373.22 3144,1399.15 3144,1410
  Layer 1 w6: v2(1540,1875) 2979,1875 2995,1859 3092,1859 3144,1807 3144,1410
  Layer 3 w6: v2(1540,1875) P1.2@1540,1950
  Layer 6 w20: P1.2@1540,1950 P11.3@1540,2100
  other v3: 1540,1875
RX1_SMISO_RX0_MSPI6_NCE2_GP2: P15.4 U1.J4 | length 752.8
  Layer 1 w3: P15.4@2655.51,1200 P15.4@2670.24,1200 ; U1.J4@3181.07,1303.45 3181.07,1304.45 3180,1305.51 3180,1324 3193,1337 v5(3201,1337)
  Layer 5 w6: P15.4@2612,1197 P15.4@2612,1217
  Layer 4 w6: P15.4@2605.51,1200 2605.51,1231.51 2711,1337 v5(3201,1337)
  other v2: 3201,1337
  other v3: 3201,1337
RxD: SB11.1 U5.40 | length 298.6
  Layer 1 w6: U5.40@1819.63,1175.16 1836.84,1175.16 U5.40@1837,1175 ; SB11.1@2100,1136.7 SB11.1@2100,1138.81
  Layer 1 w10: U5.40@1836.84,1175.16 1960.5,1175.16 1998.96,1136.7 SB11.1@2100,1136.7
SSCL_SSCK_CKO_MSPI4_NCE0_GP0: P15.3 U1.G4 | length 1138.1
  Layer 1 w3: P15.3@2455.51,1200 P15.3@2505.51,1200
  Layer 1 w6: P15.3@2505.51,1197.5 P15.3@2505.51,1200 ; P15.3@2525.01,1178 P15.3@2527.51,1178
  Layer 5 w6: P15.3@2505.51,1200 P15.3@2515.84,1189.67
  Layer 2 w6: P15.3@2505.51,1200 P15.3@2515.58,1200 ; v3(3169,1285) 3177,1285 3181,1281 v2(3181,1275.89)
  Layer 3 w6: v5(3137,1038) 3157,1038 3161.57,1042.57 3161.57,1182.86 3164,1185.29 3164,1199.78 3143.91,1219.87 3142.91,1220.89 3142.91,1242.07 3139.5,1245.48 3139.5,1260.3 3163.82,1284.62 3168.62,1284.62 v3(3169,1285)
  Layer 4 w6: P15.3@2505.51,1200 2551,1154.51 2551,1076 2576,1051 2642,1051 2655,1038 v5(3137,1038)
SSDA_SMOSI_TX0_MSPI5_NCE1_GP1: P15.1 U1.H4 | length 797.8
  Layer 1 w3: U1.H4@3181,1287.7 3173.21,1295.48 3173.21,1331 3189,1346.79 v5(3189,1354)
  Layer 1 w6: U1.H4@3181,1287.7 U1.H4@3181.07,1287.7
  Layer 3 w3: v5@3193.79,1354 v5(3189,1354) 3190,1354 3193,1351 v5@3194.89,1352.89 ; v5@3193.79,1354 v5@3194.89,1352.89 ; v5@3193.79,1354 v5@3194.89,1352.89
  Layer 4 w6: P15.1@2505.51,1300 2558.51,1353 3188,1353 v5(3189,1354)
  other v2: 3189,1354
  other v3: 3189,1354
SWDCK_NCE20_TX0_TX1_I2SB_RTS1_GP20: J1.4 P16.8 R2.2 U1.F8 U2.3 | length 4490
  Layer 1 w3: U1.F8@3116.87,1255 v2(3117.62,1255.74) U1.F8@3117.87,1256
  Layer 1 w6: U2.3@1320.43,558.78 1321.22,557.99 v1(1321.22,530.78) ; P16.8@3693,734 3709,750 P16.8@3750,750
  Layer 1 w10: P16.8@3693,734 3700,727 R2.2@3700,679.69 ; P16.8@3750,750 3756,744 3756,645 3767,634 3902,634 3930.32,605.68 3930.32,497 3940.32,487 3982,487 3984,489 J1.4@3988.77,489
  Layer 2 w3: v2(3117.62,1255.74) 3117.74,1255.74 v3@3118.07,1256.07
  Layer 3 w6: v5(3023,679) 3024,680 3024,1224 3071.21,1271.21 3110.79,1271.21 3117.62,1264.38 v2(3117.62,1255.74) ; v2(3117.62,1255.74) 3117.62,1255.38 3117.98,1255.74 v2(3117.62,1255.74)
  Layer 4 w6: v5(3023,679) 3629,679 P16.8@3700,750
  Layer 6 w6: v1(1321.22,530.78) 1347,505 3137,505 3317,685 3635,685 P16.8@3700,750
  other v3: 3117.62,1255.74
SWDIO_NCE21_RX0_RX1_SCCRST_CTS1_GP21: J1.2 P16.7 R1.2 U1.F7 U3.3 | length 3979.7
  Layer 1 w6: P16.7@3528,772 P16.7@3550,750
  Layer 1 w10: U3.3@1570.59,555.59 1579.41,555.59 1590,545 1590,515 1599,506 3437,506 3544,613 3544,752 3546,750 P16.7@3550,750 P16.7@3600,750 R1.2@3600,679.69 ; v4(3821,665) 3834,652 3953,652 3984,621 3984,543.77 J1.2@3988.77,539
  Layer 3 w5: 3098,1165.96 3098,1185 3118.56,1205.56 3118.56,1213.69 3129,1224.13 v3(3129,1257)
  Layer 3 w6: v3(3098,747) 3098,1165.96
  Layer 4 w6: v3(3098,747) 3597,747 P16.7@3600,750 3600,762 3634,796 3748,796 3821,723 v4(3821,665)
  other v2: 3129,1257
  other v5: 3098,747
SWO_NCE50_CT0_TX0_RX0_TX1_RX1_GP50: P2.8 P11.16 U1.J6 | length 3280.1
  Layer 1 w3: U1.J6@3149.57,1303.45 3150,1303.88 3150,1342.37 3149.99,1362.99 3190,1403 3190,1409
  Layer 1 w6: v1@991,1910 3119,1910 3190,1839 3190,1409
  Layer 3 w6: P11.16@940,2200 946.48,2193.51 975.49,2193.51 991,2178 v1@991,1910
  Layer 6 w3: P2.8@940,2352 938,2350 P2.8@940,2350 946,2350 P2.8@952,2356
  Layer 6 w20: P11.16@940,2200 P2.8@940,2350 P2.8@940,2352
  other v1: 990,1910
SWO_NCE61_CT11_TX0_RX0_TX1_RX1_GP61: P6.5 P13.10 U1.H6 | length 2188.6
  Layer 1 w3: U1.H6@3149.57,1287.7 3149.35,1287.92 3149.35,1292.57 3141.72,1300.2 3141.72,1369.04 3178,1405.32 3178,1409
  Layer 1 w6: v2(2052,1898) 3112,1898 3178,1832 3178,1409
  Layer 3 w6: v2(2052,1898) 2052,2152 P13.10@2100,2200
  Layer 6 w3: P6.5@2100,2349.99 2101,2348.99 P6.5@2101,2323
  Layer 6 w20: P13.10@2100,2200 2101,2201 P6.5@2101,2323
  other v3: 2052,1898
SWO_NCE62_CT12_CTS0_RTS0_CTS1_RTS1_GP62: P6.4 P13.8 U1.G6 | length 2071
  Layer 1 w3: v2(3147,1272) 3148.9,1272 3148.95,1271.95 U1.G6@3149.57,1271.95
  Layer 2 w3: v2@3146.6,1272.4 v2(3147,1272)
  Layer 2 w6: v3@3143,1294 3146.6,1290.4 v2@3146.6,1272.4
  Layer 3 w6: P13.8@2200,2200 2152,2152 2152,1913 2215,1850 2215,1770.86 2230,1755.86 2230,1375 v1(2220,1365) ; v3(3143,1293) v5(3143,1367)
  Layer 4 w6: v1(2220,1365) 3141,1365 v5(3143,1367)
  Layer 6 w20: P13.8@2199,2201 P13.8@2200,2200 2200,2347 2197.01,2349.99 P6.4@2200,2349.99
  other v8: 3143,1367
SWO_NCE63_CT13_CTS0_RTS0_CTS1_RTS1_GP63: P6.3 P13.6 U1.H7 | length 1861.1
  Layer 1 w3: U1.H7@3133.82,1287.7 3133.82,1292.35 3125.98,1300.2 3125.98,1372.64 3155,1401.66 3155,1409
  Layer 1 w6: v2(2352,1888) 2984.86,1888 3000.86,1872 3101,1872 3155,1818 3155,1409
  Layer 3 w6: P13.6@2300,2200 2352,2148 v2(2352,1888)
  Layer 6 w20: P13.6@2300,2200 P6.3@2300,2349.99
  other v3: 2352,1888
SWO_NCE69_CT19_TX0_RX0_TX1_RX1_GP69: P10.5 P17.10 U1.G9 | length 1233.9
  Layer 2 w6: v3(2954.75,1289.75) 3084.53,1289.75 v2(3102.33,1271.95)
  Layer 3 w6: v3(2954.75,1289.75) 2954.75,2154.75 P17.10@3000,2200
  Layer 6 w20: P17.10@3000,2200 P10.5@3000,2349.99
SWO_NCE70_CT20_TX0_RX0_TX1_RX1_GP70: P10.4 P17.8 U1.F9 | length 1215.2
  Layer 3 w6: v5(3032,1261) 3000,1293 3000,1829 3047,1876 3047,2147 P17.8@3100,2200
  Layer 4 w6: v5(3032,1261) 3099,1259 3101.8,1256.2 v2(3102.33,1256.2)
  Layer 6 w20: P17.8@3100,2200 P10.4@3100,2349.99
  other v3: 3102.33,1256.2
  other v5: 3102.33,1256.2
